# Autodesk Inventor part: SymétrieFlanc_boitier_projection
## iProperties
Created: 2011-01
Part Number: SymétrieFlanc_boitier_projection
Document SubType Name: Modeling
Designer: eric
Density: 1 g/cm^3
Mass: 26.857 g
Surface Area: 377.116 cm^2
Volume: 26.857 cm^3
Author: eric
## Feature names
1. Base1
